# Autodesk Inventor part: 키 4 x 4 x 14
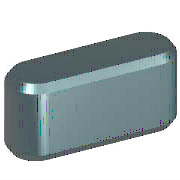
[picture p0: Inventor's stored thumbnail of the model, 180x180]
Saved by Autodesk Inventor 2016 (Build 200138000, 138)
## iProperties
IsCustomPart: 1
Created: 2012-02
Part Number: 키 4 x 4 x 14
Material: 강철, 연강
Description: 키 및 해당 키홈
Document SubType Name: Modeling
Standard: KS B 1311
Designer: mduedu
Standards Organization: KS
Language: ko-KR
Size Designation: 4 x 4 x 12
Categories: <MemberInstance><Categories><Category DisplayName="샤프트 부품" InternalName="7f7aeb1f-a693-4053-b835-cee3144e0d98" Mnemonic="SHFT"><Category DisplayName="키" Interna
Density: 1 g/cm^3
Appearance: 노란색
Author: mduedu
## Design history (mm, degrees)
workplane "Work Plane1"
workplane "Work Plane2"
sketch "스케치1"
  geometry: L1 (2, 2)-(12, 2); L2 (12, -2)-(2, -2); L3 (0, 8.8)-(0, -3.8) reference; L4 (-2.4, 0)-(14.4, 0) reference; L5 (14, 0)-(14, 7); A1 r 2 centre (2, 0) between (2, 2) and (2, -2); A2 r 2 centre (12, 0) between (12, -2) and (12, 2)
  constraints: 6 end point, 5 point on circle, 4 tangent, 3 point on line, 2 centre point, 1 horizontal, 1 parallel, 1 perpendicular
  dimensions: "d0" = 2 radius of A1 (= 0.5 x PB); "d13" = 2 radius of A2 (= 0.5 x PB); "d14" = 14 distance between parallel lines of L5 L3 (= NLG)
extrude "본체1" new body sketch "스케치1" taper "d3" = 0 deg; stored distance "d4" = 10
workplane "Work Plane3"
body "Solid1"
chamfer "모따기1" distance "d8" = 0.25 (= PHH); stored, may be unused: second distance "d9" = 0.25 (= PHH), angle "d15" = 45 deg
other parameters: "d1" = -2.5 (= -PNT), "d2" = 1.5 (= PH - PNT), "NLG" = 14 [user parameter; used in 3 equation terms], "PB" = 4 [user parameter; used in 2 equation terms], "PNT" = 2.5 [user parameter; used in 2 equation terms], "PH" = 4 [user parameter; used in 1 equation term], "PHH" = 0.25 [user parameter; used in 2 equation terms], "d10" = 0, "d16" = 0, "d17" = 0, "d18" = 0, "PLB2" = 14 (= NLG) [user parameter], "WDMAX" = 12 [user parameter], "PLB1" = 14 (= NLG) [user parameter], "RR" = 0.08 [user parameter], "PUEB" = 1.8 [user parameter]
